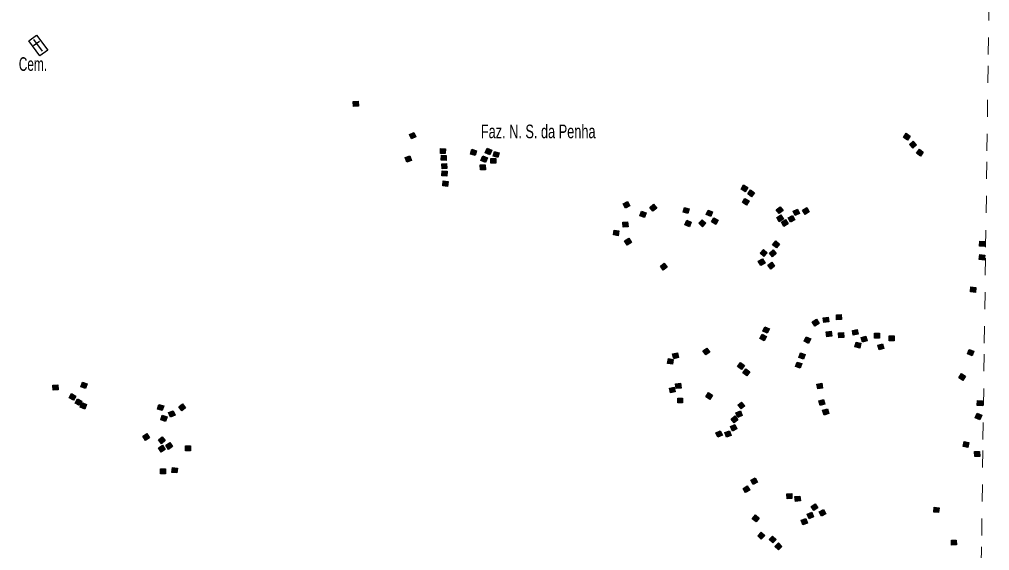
# Model space of a CAD drawing. Extents: x 679 to 705, y 7427.4 to 7455.4.
# Drawn here: x 699.1 to 704.8, y 7436.88 to 7440 of the extents above; entities that cross this region are included whole.
import ezdxf

# ---------------------------------------------------------------- set-up
doc = ezdxf.new("R2010")
doc.units = 0
doc.header["$LTSCALE"] = 0.032
doc.linetypes.add('SHORT_DASHED', pattern=[2.7, 1.5, -1.2])
for name, color, linetype, lineweight in [('2', 7, 'Continuous', 25), ('20', 7, 'Continuous', 25), ('58', 7, 'SHORT_DASHED', 13)]:
    doc.layers.add(name, color=color, linetype=linetype, lineweight=lineweight)
doc.layers.add('61', color=7, linetype='Continuous')

msp = doc.modelspace()

# ---------------------------------------------------------------- hatches: boundary and pattern name
at = {"layer": '2'}
for points in [[(701.0872, 7439.5192), (701.0898, 7439.4903), (701.061, 7439.4876), (701.0583, 7439.5165)], [(701.4151, 7439.3357), (701.4273, 7439.3094), (701.401, 7439.2972), (701.3888, 7439.3235)], [(704.3092, 7439.33), (704.3333, 7439.3139), (704.3172, 7439.2898), (704.2931, 7439.3059)], [(704.35, 7439.2841), (704.3701, 7439.2633), (704.3493, 7439.2431), (704.3291, 7439.264)], [(701.3917, 7439.1977), (701.4008, 7439.1701), (701.3733, 7439.161), (701.3641, 7439.1885)], [(701.6016, 7439.2396), (701.5999, 7439.2106), (701.571, 7439.2123), (701.5726, 7439.2412)], [(701.6059, 7439.2002), (701.6053, 7439.1712), (701.5763, 7439.1719), (701.5769, 7439.2008)], [(701.7844, 7439.2279), (701.7761, 7439.2002), (701.7483, 7439.2085), (701.7566, 7439.2363)], [(701.8477, 7439.1858), (701.8359, 7439.1593), (701.8094, 7439.1711), (701.8212, 7439.1976)], [(701.8731, 7439.2307), (701.8616, 7439.2041), (701.835, 7439.2155), (701.8464, 7439.2422)], [(701.9168, 7439.2152), (701.9084, 7439.1874), (701.8806, 7439.1957), (701.889, 7439.2235)], [(704.3868, 7439.236), (704.41, 7439.2186), (704.3925, 7439.1954), (704.3693, 7439.2129)], [(701.6078, 7439.1519), (701.6098, 7439.123), (701.5808, 7439.121), (701.5789, 7439.15)], [(701.8347, 7439.1451), (701.8357, 7439.1161), (701.8067, 7439.1151), (701.8057, 7439.1441)], [(701.8974, 7439.1829), (701.8974, 7439.1539), (701.8684, 7439.1539), (701.8684, 7439.1829)], [(701.6114, 7439.1069), (701.6093, 7439.078), (701.5803, 7439.0801), (701.5824, 7439.109)], [(701.6165, 7439.0475), (701.6135, 7439.0186), (701.5847, 7439.0216), (701.5877, 7439.0505)], [(703.3525, 7439.0265), (703.3778, 7439.0123), (703.3637, 7438.987), (703.3384, 7439.0012)], [(703.3948, 7438.9983), (703.4181, 7438.981), (703.4008, 7438.9577), (703.3775, 7438.975)], [(702.6717, 7438.9302), (702.6854, 7438.9046), (702.6598, 7438.8909), (702.6461, 7438.9165)], [(702.8243, 7438.9133), (702.8426, 7438.8908), (702.8201, 7438.8725), (702.8018, 7438.895)], [(703.3614, 7438.9479), (703.3862, 7438.9328), (703.3711, 7438.908), (703.3464, 7438.9231)], [(702.7811, 7438.8625), (702.7711, 7438.8353), (702.7438, 7438.8453), (702.7538, 7438.8725)], [(703.006, 7438.895), (703.0338, 7438.8867), (703.0256, 7438.8589), (702.9978, 7438.8671)], [(703.1443, 7438.8796), (703.1715, 7438.8695), (703.1614, 7438.8423), (703.1342, 7438.8524)], [(703.5681, 7438.8989), (703.5854, 7438.8757), (703.5622, 7438.8583), (703.5448, 7438.8815)], [(703.6709, 7438.8852), (703.683, 7438.8588), (703.6566, 7438.8467), (703.6446, 7438.8731)], [(703.7243, 7438.8938), (703.7397, 7438.8693), (703.7152, 7438.8538), (703.6997, 7438.8784)], [(702.6718, 7438.8104), (702.675, 7438.7816), (702.6462, 7438.7784), (702.643, 7438.8072)], [(703.019, 7438.8193), (703.0458, 7438.8082), (703.0347, 7438.7814), (703.0079, 7438.7924)], [(703.1105, 7438.8224), (703.1314, 7438.8023), (703.1113, 7438.7814), (703.0904, 7438.8016)], [(703.1794, 7438.8345), (703.2044, 7438.8198), (703.1897, 7438.7948), (703.1647, 7438.8095)], [(703.5734, 7438.8506), (703.5881, 7438.8256), (703.5631, 7438.8109), (703.5484, 7438.8359)], [(703.5999, 7438.8236), (703.6154, 7438.7991), (703.5909, 7438.7836), (703.5754, 7438.8081)], [(703.6416, 7438.8471), (703.6546, 7438.8211), (703.6286, 7438.8082), (703.6157, 7438.8341)], [(702.6211, 7438.7575), (702.617, 7438.7288), (702.5883, 7438.7329), (702.5924, 7438.7616)], [(702.6781, 7438.7136), (702.6938, 7438.6892), (702.6695, 7438.6735), (702.6538, 7438.6979)], [(703.5425, 7438.6979), (703.5651, 7438.6796), (703.5469, 7438.6571), (703.5243, 7438.6753)], [(704.7709, 7438.6947), (704.7689, 7438.6658), (704.7399, 7438.6679), (704.742, 7438.6968)], [(703.47, 7438.6469), (703.4918, 7438.6277), (703.4726, 7438.606), (703.4508, 7438.6252)], [(703.5269, 7438.6453), (703.5458, 7438.6233), (703.5238, 7438.6044), (703.5049, 7438.6265)], [(703.4655, 7438.5936), (703.4795, 7438.5682), (703.454, 7438.5542), (703.4401, 7438.5797)], [(703.5186, 7438.5734), (703.536, 7438.5502), (703.5128, 7438.5328), (703.4954, 7438.556)], [(704.7716, 7438.6142), (704.768, 7438.5854), (704.7392, 7438.589), (704.7428, 7438.6178)], [(702.8874, 7438.567), (702.9046, 7438.5436), (702.8812, 7438.5265), (702.8641, 7438.5498)], [(704.7186, 7438.4247), (704.7159, 7438.3959), (704.687, 7438.3986), (704.6898, 7438.4275)], [(703.7821, 7438.2379), (703.7975, 7438.2133), (703.7729, 7438.1979), (703.7575, 7438.2225)], [(703.8501, 7438.2505), (703.854, 7438.2217), (703.8252, 7438.2179), (703.8214, 7438.2466)], [(703.9278, 7438.2655), (703.9295, 7438.2366), (703.9005, 7438.2349), (703.8988, 7438.2638)], [(703.4792, 7438.1942), (703.5051, 7438.1812), (703.4921, 7438.1553), (703.4662, 7438.1682)], [(704.0213, 7438.1778), (704.027, 7438.1494), (703.9986, 7438.1437), (703.9929, 7438.1721)], [(703.4619, 7438.1496), (703.4877, 7438.1362), (703.4743, 7438.1105), (703.4485, 7438.1239)], [(703.7483, 7438.122), (703.7359, 7438.0958), (703.7097, 7438.1082), (703.7221, 7438.1344)], [(703.8674, 7438.1677), (703.8718, 7438.1391), (703.8431, 7438.1347), (703.8387, 7438.1633)], [(703.9402, 7438.1605), (703.9426, 7438.1316), (703.9137, 7438.1292), (703.9113, 7438.1581)], [(704.0726, 7438.1387), (704.0805, 7438.1108), (704.0527, 7438.1029), (704.0447, 7438.1307)], [(704.1518, 7438.1563), (704.1518, 7438.1273), (704.1228, 7438.1273), (704.1228, 7438.1563)], [(704.2379, 7438.1403), (704.2379, 7438.1113), (704.2089, 7438.1113), (704.2089, 7438.1403)], [(703.1381, 7438.0689), (703.1545, 7438.045), (703.1306, 7438.0286), (703.1141, 7438.0525)], [(704.0431, 7438.0969), (704.0364, 7438.0687), (704.0082, 7438.0754), (704.0149, 7438.1036)], [(704.1698, 7438.094), (704.1778, 7438.0661), (704.1499, 7438.0582), (704.1419, 7438.0861)], [(704.6792, 7438.061), (704.7064, 7438.0508), (704.6962, 7438.0237), (704.669, 7438.0338)], [(702.9399, 7438.0023), (702.9352, 7437.9737), (702.9066, 7437.9784), (702.9113, 7438.007)], [(702.9642, 7438.0411), (702.9715, 7438.0131), (702.9434, 7438.0058), (702.9361, 7438.0339)], [(703.7155, 7438.0316), (703.7063, 7438.0041), (703.6788, 7438.0133), (703.688, 7438.0408)], [(703.3356, 7437.9828), (703.359, 7437.9657), (703.342, 7437.9423), (703.3185, 7437.9593)], [(703.3663, 7437.9461), (703.3894, 7437.9286), (703.3718, 7437.9055), (703.3487, 7437.923)], [(703.6949, 7437.9771), (703.6853, 7437.9497), (703.6579, 7437.9594), (703.6676, 7437.9867)], [(704.6338, 7437.9188), (704.6581, 7437.9029), (704.6422, 7437.8786), (704.6179, 7437.8945)], [(699.3223, 7437.8522), (699.3241, 7437.8233), (699.2951, 7437.8215), (699.2933, 7437.8504)], [(699.4946, 7437.8584), (699.4843, 7437.8313), (699.4572, 7437.8417), (699.4675, 7437.8688)], [(702.9456, 7437.8398), (702.952, 7437.8115), (702.9237, 7437.8051), (702.9173, 7437.8334)], [(702.9822, 7437.8627), (702.9858, 7437.8339), (702.9571, 7437.8303), (702.9535, 7437.8591)], [(703.8129, 7437.8616), (703.8178, 7437.833), (703.7892, 7437.8281), (703.7843, 7437.8567)], [(699.4288, 7437.7869), (699.4142, 7437.7618), (699.3891, 7437.7764), (699.4037, 7437.8015)], [(702.9952, 7437.775), (702.9952, 7437.746), (702.9662, 7437.746), (702.9662, 7437.775)], [(703.1464, 7437.8071), (703.1707, 7437.7914), (703.1551, 7437.767), (703.1307, 7437.7827)], [(699.4638, 7437.7568), (699.4495, 7437.7315), (699.4243, 7437.7458), (699.4386, 7437.7711)], [(699.4918, 7437.7364), (699.4803, 7437.7098), (699.4537, 7437.7213), (699.4652, 7437.7479)], [(699.9449, 7437.7288), (699.9364, 7437.7011), (699.9087, 7437.7095), (699.9171, 7437.7372)], [(700.0561, 7437.7403), (700.0738, 7437.7173), (700.0508, 7437.6996), (700.0331, 7437.7226)], [(703.3415, 7437.7517), (703.3606, 7437.7299), (703.3387, 7437.7108), (703.3197, 7437.7326)], [(703.8235, 7437.7671), (703.832, 7437.7394), (703.8043, 7437.7309), (703.7958, 7437.7586)], [(704.7578, 7437.758), (704.7556, 7437.729), (704.7267, 7437.7312), (704.7289, 7437.7601)], [(699.9642, 7437.6646), (699.9552, 7437.6371), (699.9276, 7437.6461), (699.9367, 7437.6736)], [(700.0008, 7437.7006), (700.0114, 7437.6736), (699.9844, 7437.663), (699.9738, 7437.69)], [(703.3022, 7437.6703), (703.3206, 7437.6479), (703.2983, 7437.6295), (703.2798, 7437.6518)], [(703.3348, 7437.6993), (703.346, 7437.6726), (703.3193, 7437.6614), (703.3081, 7437.6881)], [(703.846, 7437.7112), (703.8543, 7437.6834), (703.8265, 7437.6751), (703.8182, 7437.7029)], [(704.753, 7437.6749), (704.7424, 7437.6479), (704.7154, 7437.6585), (704.726, 7437.6855)], [(703.3022, 7437.6198), (703.3144, 7437.5935), (703.2881, 7437.5813), (703.2759, 7437.6076)], [(699.8457, 7437.5662), (699.8618, 7437.542), (699.8377, 7437.526), (699.8216, 7437.5501)], [(699.936, 7437.5474), (699.9543, 7437.5249), (699.9318, 7437.5066), (699.9135, 7437.5291)], [(703.2156, 7437.5833), (703.2286, 7437.5573), (703.2026, 7437.5444), (703.1897, 7437.5703)], [(703.2706, 7437.5823), (703.28, 7437.5549), (703.2526, 7437.5455), (703.2432, 7437.5729)], [(699.9383, 7437.4976), (699.9538, 7437.4731), (699.9293, 7437.4576), (699.9138, 7437.4821)], [(699.9806, 7437.5137), (699.997, 7437.4898), (699.9731, 7437.4734), (699.9567, 7437.4973)], [(700.1025, 7437.4942), (700.1025, 7437.4652), (700.0735, 7437.4652), (700.0735, 7437.4942)], [(704.6779, 7437.5137), (704.6724, 7437.4852), (704.6439, 7437.4907), (704.6494, 7437.5192)], [(704.7403, 7437.4611), (704.7414, 7437.4322), (704.7124, 7437.4311), (704.7113, 7437.4601)], [(699.955, 7437.3597), (699.955, 7437.3307), (699.926, 7437.3307), (699.926, 7437.3597)], [(700.0253, 7437.3636), (700.0219, 7437.3348), (699.9931, 7437.3382), (699.9965, 7437.367)], [(703.375, 7437.2592), (703.3899, 7437.2343), (703.3651, 7437.2194), (703.3502, 7437.2443)], [(703.4209, 7437.3068), (703.4346, 7437.2812), (703.4091, 7437.2675), (703.3953, 7437.293)], [(703.6364, 7437.2141), (703.6377, 7437.1851), (703.6088, 7437.1838), (703.6074, 7437.2127)], [(703.6845, 7437.1995), (703.6879, 7437.1707), (703.6591, 7437.1673), (703.6557, 7437.1961)], [(703.7752, 7437.1538), (703.7905, 7437.1292), (703.7659, 7437.1139), (703.7506, 7437.1385)], [(703.4234, 7437.0881), (703.4456, 7437.0695), (703.427, 7437.0472), (703.4048, 7437.0659)], [(703.7543, 7437.1037), (703.7654, 7437.0769), (703.7386, 7437.0658), (703.7275, 7437.0926)], [(703.8242, 7437.1198), (703.8379, 7437.0942), (703.8123, 7437.0805), (703.7986, 7437.1061)], [(704.5025, 7437.1308), (704.5001, 7437.1019), (704.4712, 7437.1042), (704.4736, 7437.1331)], [(703.7189, 7437.0667), (703.7283, 7437.0393), (703.7009, 7437.0298), (703.6915, 7437.0572)], [(703.4572, 7436.987), (703.478, 7436.9667), (703.4577, 7436.946), (703.4369, 7436.9662)], [(703.5242, 7436.9644), (703.5454, 7436.9447), (703.5256, 7436.9235), (703.5044, 7436.9432)], [(703.5582, 7436.9237), (703.5791, 7436.9036), (703.5591, 7436.8827), (703.5381, 7436.9027)], [(704.6038, 7436.9409), (704.6042, 7436.9119), (704.5752, 7436.9115), (704.5748, 7436.9405)]]:
    msp.add_hatch(color=256, dxfattribs=at).paths.add_polyline_path(points)

# ---------------------------------------------------------------- linework, layer by layer
for points in [[(701.0872, 7439.5192), (701.0898, 7439.4903), (701.061, 7439.4876), (701.0583, 7439.5165)], [(701.4151, 7439.3357), (701.4273, 7439.3094), (701.401, 7439.2972), (701.3888, 7439.3235)], [(704.3092, 7439.33), (704.3333, 7439.3139), (704.3172, 7439.2898), (704.2931, 7439.3059)], [(704.35, 7439.2841), (704.3701, 7439.2633), (704.3493, 7439.2431), (704.3291, 7439.264)], [(701.3917, 7439.1977), (701.4008, 7439.1701), (701.3733, 7439.161), (701.3641, 7439.1885)], [(701.6016, 7439.2396), (701.5999, 7439.2106), (701.571, 7439.2123), (701.5726, 7439.2412)], [(701.6059, 7439.2002), (701.6053, 7439.1712), (701.5763, 7439.1719), (701.5769, 7439.2008)], [(701.7844, 7439.2279), (701.7761, 7439.2002), (701.7483, 7439.2085), (701.7566, 7439.2363)], [(701.8477, 7439.1858), (701.8359, 7439.1593), (701.8094, 7439.1711), (701.8212, 7439.1976)], [(701.8731, 7439.2307), (701.8616, 7439.2041), (701.835, 7439.2155), (701.8464, 7439.2422)], [(701.9168, 7439.2152), (701.9084, 7439.1874), (701.8806, 7439.1957), (701.889, 7439.2235)], [(704.3868, 7439.236), (704.41, 7439.2186), (704.3925, 7439.1954), (704.3693, 7439.2129)], [(701.6078, 7439.1519), (701.6098, 7439.123), (701.5808, 7439.121), (701.5789, 7439.15)], [(701.8347, 7439.1451), (701.8357, 7439.1161), (701.8067, 7439.1151), (701.8057, 7439.1441)], [(701.8974, 7439.1829), (701.8974, 7439.1539), (701.8684, 7439.1539), (701.8684, 7439.1829)], [(701.6114, 7439.1069), (701.6093, 7439.078), (701.5803, 7439.0801), (701.5824, 7439.109)], [(701.6165, 7439.0475), (701.6135, 7439.0186), (701.5847, 7439.0216), (701.5877, 7439.0505)], [(703.3525, 7439.0265), (703.3778, 7439.0123), (703.3637, 7438.987), (703.3384, 7439.0012)], [(703.3948, 7438.9983), (703.4181, 7438.981), (703.4008, 7438.9577), (703.3775, 7438.975)], [(702.6717, 7438.9302), (702.6854, 7438.9046), (702.6598, 7438.8909), (702.6461, 7438.9165)], [(702.8243, 7438.9133), (702.8426, 7438.8908), (702.8201, 7438.8725), (702.8018, 7438.895)], [(703.3614, 7438.9479), (703.3862, 7438.9328), (703.3711, 7438.908), (703.3464, 7438.9231)], [(702.7811, 7438.8625), (702.7711, 7438.8353), (702.7438, 7438.8453), (702.7538, 7438.8725)], [(703.006, 7438.895), (703.0338, 7438.8867), (703.0256, 7438.8589), (702.9978, 7438.8671)], [(703.1443, 7438.8796), (703.1715, 7438.8695), (703.1614, 7438.8423), (703.1342, 7438.8524)], [(703.5681, 7438.8989), (703.5854, 7438.8757), (703.5622, 7438.8583), (703.5448, 7438.8815)], [(703.6709, 7438.8852), (703.683, 7438.8588), (703.6566, 7438.8467), (703.6446, 7438.8731)], [(703.7243, 7438.8938), (703.7397, 7438.8693), (703.7152, 7438.8538), (703.6997, 7438.8784)], [(702.6718, 7438.8104), (702.675, 7438.7816), (702.6462, 7438.7784), (702.643, 7438.8072)], [(703.019, 7438.8193), (703.0458, 7438.8082), (703.0347, 7438.7814), (703.0079, 7438.7924)], [(703.1105, 7438.8224), (703.1314, 7438.8023), (703.1113, 7438.7814), (703.0904, 7438.8016)], [(703.1794, 7438.8345), (703.2044, 7438.8198), (703.1897, 7438.7948), (703.1647, 7438.8095)], [(703.5734, 7438.8506), (703.5881, 7438.8256), (703.5631, 7438.8109), (703.5484, 7438.8359)], [(703.5999, 7438.8236), (703.6154, 7438.7991), (703.5909, 7438.7836), (703.5754, 7438.8081)], [(703.6416, 7438.8471), (703.6546, 7438.8211), (703.6286, 7438.8082), (703.6157, 7438.8341)], [(702.6211, 7438.7575), (702.617, 7438.7288), (702.5883, 7438.7329), (702.5924, 7438.7616)], [(702.6781, 7438.7136), (702.6938, 7438.6892), (702.6695, 7438.6735), (702.6538, 7438.6979)], [(703.5425, 7438.6979), (703.5651, 7438.6796), (703.5469, 7438.6571), (703.5243, 7438.6753)], [(704.7709, 7438.6947), (704.7689, 7438.6658), (704.7399, 7438.6679), (704.742, 7438.6968)], [(703.47, 7438.6469), (703.4918, 7438.6277), (703.4726, 7438.606), (703.4508, 7438.6252)], [(703.5269, 7438.6453), (703.5458, 7438.6233), (703.5238, 7438.6044), (703.5049, 7438.6265)], [(703.4655, 7438.5936), (703.4795, 7438.5682), (703.454, 7438.5542), (703.4401, 7438.5797)], [(703.5186, 7438.5734), (703.536, 7438.5502), (703.5128, 7438.5328), (703.4954, 7438.556)], [(704.7716, 7438.6142), (704.768, 7438.5854), (704.7392, 7438.589), (704.7428, 7438.6178)], [(702.8874, 7438.567), (702.9046, 7438.5436), (702.8812, 7438.5265), (702.8641, 7438.5498)], [(704.7186, 7438.4247), (704.7159, 7438.3959), (704.687, 7438.3986), (704.6898, 7438.4275)], [(703.7821, 7438.2379), (703.7975, 7438.2133), (703.7729, 7438.1979), (703.7575, 7438.2225)], [(703.8501, 7438.2505), (703.854, 7438.2217), (703.8252, 7438.2179), (703.8214, 7438.2466)], [(703.9278, 7438.2655), (703.9295, 7438.2366), (703.9005, 7438.2349), (703.8988, 7438.2638)], [(703.4792, 7438.1942), (703.5051, 7438.1812), (703.4921, 7438.1553), (703.4662, 7438.1682)], [(704.0213, 7438.1778), (704.027, 7438.1494), (703.9986, 7438.1437), (703.9929, 7438.1721)], [(703.4619, 7438.1496), (703.4877, 7438.1362), (703.4743, 7438.1105), (703.4485, 7438.1239)], [(703.7483, 7438.122), (703.7359, 7438.0958), (703.7097, 7438.1082), (703.7221, 7438.1344)], [(703.8674, 7438.1677), (703.8718, 7438.1391), (703.8431, 7438.1347), (703.8387, 7438.1633)], [(703.9402, 7438.1605), (703.9426, 7438.1316), (703.9137, 7438.1292), (703.9113, 7438.1581)], [(704.0726, 7438.1387), (704.0805, 7438.1108), (704.0527, 7438.1029), (704.0447, 7438.1307)], [(704.1518, 7438.1563), (704.1518, 7438.1273), (704.1228, 7438.1273), (704.1228, 7438.1563)], [(704.2379, 7438.1403), (704.2379, 7438.1113), (704.2089, 7438.1113), (704.2089, 7438.1403)], [(703.1381, 7438.0689), (703.1545, 7438.045), (703.1306, 7438.0286), (703.1141, 7438.0525)], [(704.0431, 7438.0969), (704.0364, 7438.0687), (704.0082, 7438.0754), (704.0149, 7438.1036)], [(704.1698, 7438.094), (704.1778, 7438.0661), (704.1499, 7438.0582), (704.1419, 7438.0861)], [(704.6792, 7438.061), (704.7064, 7438.0508), (704.6962, 7438.0237), (704.669, 7438.0338)], [(702.9399, 7438.0023), (702.9352, 7437.9737), (702.9066, 7437.9784), (702.9113, 7438.007)], [(702.9642, 7438.0411), (702.9715, 7438.0131), (702.9434, 7438.0058), (702.9361, 7438.0339)], [(703.7155, 7438.0316), (703.7063, 7438.0041), (703.6788, 7438.0133), (703.688, 7438.0408)], [(703.3356, 7437.9828), (703.359, 7437.9657), (703.342, 7437.9423), (703.3185, 7437.9593)], [(703.3663, 7437.9461), (703.3894, 7437.9286), (703.3718, 7437.9055), (703.3487, 7437.923)], [(703.6949, 7437.9771), (703.6853, 7437.9497), (703.6579, 7437.9594), (703.6676, 7437.9867)], [(704.6338, 7437.9188), (704.6581, 7437.9029), (704.6422, 7437.8786), (704.6179, 7437.8945)], [(699.3223, 7437.8522), (699.3241, 7437.8233), (699.2951, 7437.8215), (699.2933, 7437.8504)], [(699.4946, 7437.8584), (699.4843, 7437.8313), (699.4572, 7437.8417), (699.4675, 7437.8688)], [(702.9456, 7437.8398), (702.952, 7437.8115), (702.9237, 7437.8051), (702.9173, 7437.8334)], [(702.9822, 7437.8627), (702.9858, 7437.8339), (702.9571, 7437.8303), (702.9535, 7437.8591)], [(703.8129, 7437.8616), (703.8178, 7437.833), (703.7892, 7437.8281), (703.7843, 7437.8567)], [(699.4288, 7437.7869), (699.4142, 7437.7618), (699.3891, 7437.7764), (699.4037, 7437.8015)], [(702.9952, 7437.775), (702.9952, 7437.746), (702.9662, 7437.746), (702.9662, 7437.775)], [(703.1464, 7437.8071), (703.1707, 7437.7914), (703.1551, 7437.767), (703.1307, 7437.7827)], [(699.4638, 7437.7568), (699.4495, 7437.7315), (699.4243, 7437.7458), (699.4386, 7437.7711)], [(699.4918, 7437.7364), (699.4803, 7437.7098), (699.4537, 7437.7213), (699.4652, 7437.7479)], [(699.9449, 7437.7288), (699.9364, 7437.7011), (699.9087, 7437.7095), (699.9171, 7437.7372)], [(700.0561, 7437.7403), (700.0738, 7437.7173), (700.0508, 7437.6996), (700.0331, 7437.7226)], [(703.3415, 7437.7517), (703.3606, 7437.7299), (703.3387, 7437.7108), (703.3197, 7437.7326)], [(703.8235, 7437.7671), (703.832, 7437.7394), (703.8043, 7437.7309), (703.7958, 7437.7586)], [(704.7578, 7437.758), (704.7556, 7437.729), (704.7267, 7437.7312), (704.7289, 7437.7601)], [(699.9642, 7437.6646), (699.9552, 7437.6371), (699.9276, 7437.6461), (699.9367, 7437.6736)], [(700.0008, 7437.7006), (700.0114, 7437.6736), (699.9844, 7437.663), (699.9738, 7437.69)], [(703.3022, 7437.6703), (703.3206, 7437.6479), (703.2983, 7437.6295), (703.2798, 7437.6518)], [(703.3348, 7437.6993), (703.346, 7437.6726), (703.3193, 7437.6614), (703.3081, 7437.6881)], [(703.846, 7437.7112), (703.8543, 7437.6834), (703.8265, 7437.6751), (703.8182, 7437.7029)], [(704.753, 7437.6749), (704.7424, 7437.6479), (704.7154, 7437.6585), (704.726, 7437.6855)], [(703.3022, 7437.6198), (703.3144, 7437.5935), (703.2881, 7437.5813), (703.2759, 7437.6076)], [(699.8457, 7437.5662), (699.8618, 7437.542), (699.8377, 7437.526), (699.8216, 7437.5501)], [(699.936, 7437.5474), (699.9543, 7437.5249), (699.9318, 7437.5066), (699.9135, 7437.5291)], [(703.2156, 7437.5833), (703.2286, 7437.5573), (703.2026, 7437.5444), (703.1897, 7437.5703)], [(703.2706, 7437.5823), (703.28, 7437.5549), (703.2526, 7437.5455), (703.2432, 7437.5729)], [(699.9383, 7437.4976), (699.9538, 7437.4731), (699.9293, 7437.4576), (699.9138, 7437.4821)], [(699.9806, 7437.5137), (699.997, 7437.4898), (699.9731, 7437.4734), (699.9567, 7437.4973)], [(700.1025, 7437.4942), (700.1025, 7437.4652), (700.0735, 7437.4652), (700.0735, 7437.4942)], [(704.6779, 7437.5137), (704.6724, 7437.4852), (704.6439, 7437.4907), (704.6494, 7437.5192)], [(704.7403, 7437.4611), (704.7414, 7437.4322), (704.7124, 7437.4311), (704.7113, 7437.4601)], [(699.955, 7437.3597), (699.955, 7437.3307), (699.926, 7437.3307), (699.926, 7437.3597)], [(700.0253, 7437.3636), (700.0219, 7437.3348), (699.9931, 7437.3382), (699.9965, 7437.367)], [(703.375, 7437.2592), (703.3899, 7437.2343), (703.3651, 7437.2194), (703.3502, 7437.2443)], [(703.4209, 7437.3068), (703.4346, 7437.2812), (703.4091, 7437.2675), (703.3953, 7437.293)], [(703.6364, 7437.2141), (703.6377, 7437.1851), (703.6088, 7437.1838), (703.6074, 7437.2127)], [(703.6845, 7437.1995), (703.6879, 7437.1707), (703.6591, 7437.1673), (703.6557, 7437.1961)], [(703.7752, 7437.1538), (703.7905, 7437.1292), (703.7659, 7437.1139), (703.7506, 7437.1385)], [(703.4234, 7437.0881), (703.4456, 7437.0695), (703.427, 7437.0472), (703.4048, 7437.0659)], [(703.7543, 7437.1037), (703.7654, 7437.0769), (703.7386, 7437.0658), (703.7275, 7437.0926)], [(703.8242, 7437.1198), (703.8379, 7437.0942), (703.8123, 7437.0805), (703.7986, 7437.1061)], [(704.5025, 7437.1308), (704.5001, 7437.1019), (704.4712, 7437.1042), (704.4736, 7437.1331)], [(703.7189, 7437.0667), (703.7283, 7437.0393), (703.7009, 7437.0298), (703.6915, 7437.0572)], [(703.4572, 7436.987), (703.478, 7436.9667), (703.4577, 7436.946), (703.4369, 7436.9662)], [(703.5242, 7436.9644), (703.5454, 7436.9447), (703.5256, 7436.9235), (703.5044, 7436.9432)], [(703.5582, 7436.9237), (703.5791, 7436.9036), (703.5591, 7436.8827), (703.5381, 7436.9027)], [(704.6038, 7436.9409), (704.6042, 7436.9119), (704.5752, 7436.9115), (704.5748, 7436.9405)]]:
    msp.add_lwpolyline(points, close=True, dxfattribs=at)
at = {"layer": '20'}
for p, q in [((699.1801, 7439.8466), (699.2143, 7439.8723)), ((699.2322, 7439.8133), (699.182, 7439.8802))]:
    msp.add_line(p, q, dxfattribs=at)
msp.add_lwpolyline([(699.1514, 7439.8731), (699.1969, 7439.9072), (699.2631, 7439.819), (699.2176, 7439.7849)], close=True, dxfattribs=at)
at = {"layer": '58'}
msp.add_lwpolyline([(704.6209, 7427.3609), (704.6287, 7427.926), (704.6365, 7428.491), (704.6443, 7429.0561), (704.652, 7429.6212), (704.6598, 7430.1862), (704.6676, 7430.7513), (704.6754, 7431.3163), (704.6832, 7431.8814), (704.6909, 7432.4465), (704.6987, 7433.0115), (704.7065, 7433.5766), (704.7143, 7434.1416), (704.722, 7434.7067), (704.7298, 7435.2717), (704.7376, 7435.8368), (704.7453, 7436.4019), (704.7531, 7436.9669), (704.7608, 7437.532), (704.7686, 7438.097), (704.7764, 7438.6621), (704.7841, 7439.2271), (704.7919, 7439.7922), (704.7996, 7440.3572)], dxfattribs=at)

# ---------------------------------------------------------------- texts
at = {"layer": '61'}
for s, width, p in [('Cem.', 0.65, (699.093, 7439.6969)), ('Faz. N. S. da Penha', 0.7, (701.8089, 7439.3012))]:
    msp.add_text(s, height=0.08, dxfattribs=dict(at, width=width)).set_placement(p)

doc.saveas('drawing.dxf')
